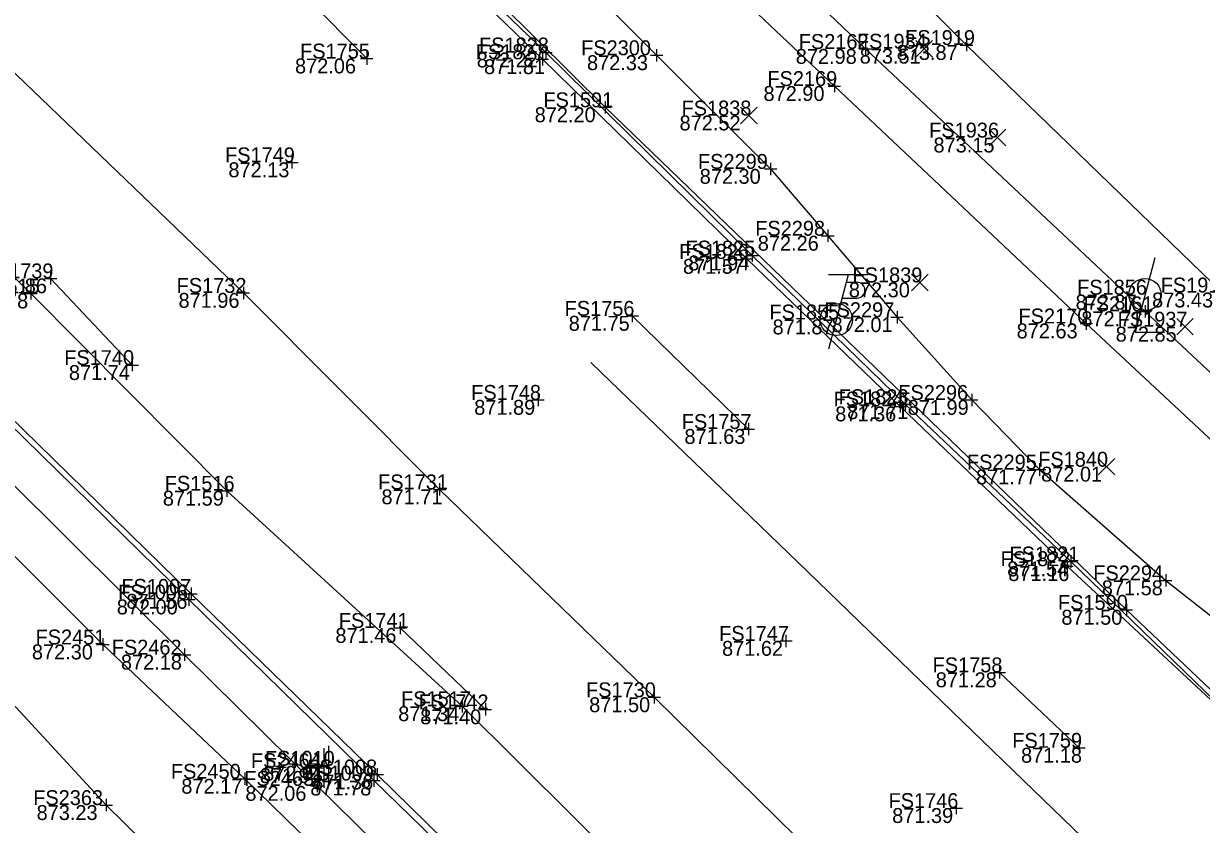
# Model space of a CAD drawing. Extents: x 1479420 to 1479833, y 379731 to 380103.
# Drawn here: x 1479498.2 to 1479593, y 379987.2 to 380051.7 of the extents above; entities that cross this region are included whole.
import ezdxf

# ---------------------------------------------------------------- set-up
doc = ezdxf.new("R2010")
doc.units = 0
for name, color, linetype in [('LT_X_Poles', 7, 'Continuous'), ('PM_X_Channelizing_Line', 7, 'Continuous'), ('PM_X_CL_Double_Solid', 7, 'Continuous'), ('PM_X_Lane_Line', 7, 'Continuous'), ('PV_X_Curb', 7, 'Continuous'), ('PV_X_Walk', 7, 'Continuous'), ('SN_X_Public', 7, 'Continuous'), ('SV_X_Break_Lines', 7, 'Continuous'), ('SV_X_Random_Point', 7, 'Continuous'), ('SV_X_Shot_Marker', 7, 'Continuous'), ('SV_X_Text_Elevation', 7, 'Continuous'), ('SV_X_Text_Name', 7, 'Continuous'), ('UT_X_Gas', 7, 'Continuous'), ('UT_X_Misc_Cells', 7, 'Continuous'), ('UT_X_Water', 7, 'Continuous')]:
    doc.layers.add(name, color=color, linetype=linetype)

msp = doc.modelspace()

# ---------------------------------------------------------------- linework, layer by layer
at = {"layer": 'LT_X_Poles'}
msp.add_lwpolyline([(1479589.196, 380032.83), (1479587.621, 380026.845), (1479589.984, 380026.845)], dxfattribs=at)
msp.add_circle((1479588.409, 380029.877), 1.3, dxfattribs=at)
at = {"layer": 'PM_X_Channelizing_Line'}
msp.add_lwpolyline([(1479582.673, 379963.806), (1479570.271, 379976.458), (1479548.912, 379997.457), (1479531.64, 380014.197), (1479515.852, 380030.017), (1479497.57, 380047.609), (1479484.703, 380060.356), (1479474.973, 380069.833)], dxfattribs=at)
at = {"layer": 'PM_X_CL_Double_Solid'}
msp.add_lwpolyline([(1479649.77, 379921.473), (1479632.094, 379938.759), (1479618.381, 379952.22), (1479598.438, 379971.627), (1479578.627, 379990.753), (1479560.467, 380008.345), (1479543.803, 380024.417)], dxfattribs=at)
at = {"layer": 'PM_X_Lane_Line'}
for p, q in [((1479518.914, 380055.834), (1479525.775, 380048.891)), ((1479500.335, 380031.188), (1479506.907, 380024.206)), ((1479547.143, 380028.17), (1479556.493, 380019.059)), ((1479528.47, 380003.039), (1479535.323, 379996.483)), ((1479576.693, 379999.465), (1479583.102, 379993.389))]:
    msp.add_line(p, q, dxfattribs=at)
at = {"layer": 'PV_X_Curb'}
for points in [[(1479795.994, 380033.189), (1479773.609, 380022.189), (1479753.08, 380012.28), (1479732.582, 380002.187), (1479709.578, 379990.944), (1479686.038, 379979.568), (1479675.424, 379995.638), (1479673.845, 379997.042), (1479672.388, 379997.402), (1479671.072, 379997.477), (1479668.749, 379997.507), (1479666.577, 379997.444), (1479665.261, 379997.435), (1479663.761, 379996.907), (1479662.621, 379996.118), (1479646.813, 379979.589), (1479631.39, 379994.413), (1479612.948, 380012.393), (1479594.615, 380030.048), (1479574.047, 380049.976), (1479559.355, 380064.639), (1479550.33, 380073.358), (1479530.481, 380092.839), (1479523.351, 380099.687)], [(1479620.557, 379971.482), (1479582.44, 380008.391), (1479569.122, 380021.057), (1479556.793, 380033.025), (1479540.187, 380049.375), (1479522.156, 380066.75), (1479503.679, 380084.635)], [(1479602.178, 379989.373), (1479582.142, 380008.015), (1479568.704, 380020.876), (1479556.358, 380032.756), (1479539.916, 380048.835), (1479521.67, 380066.459), (1479503.182, 380084.417)], [(1479465.217, 380050.646), (1479478.531, 380037.631), (1479495.524, 380020.938), (1479511.459, 380005.334), (1479526.353, 379990.752), (1479540.932, 379976.569), (1479555.934, 379961.972), (1479555.892, 379961.631), (1479559.685, 379957.777), (1479564.545, 379952.777), (1479567.017, 379949.687), (1479570.003, 379944.359), (1479571.368, 379941.515), (1479571.64, 379940.628), (1479572.403, 379938.2), (1479572.729, 379936.736), (1479572.917, 379935.416), (1479573.286, 379931.116), (1479573.281, 379927.358), (1479572.586, 379922.13), (1479571.403, 379917.504), (1479569.157, 379912.511), (1479566.948, 379909.055), (1479563.851, 379905.522)], [(1479465.43, 380051.173), (1479478.923, 380037.911), (1479495.631, 380021.426), (1479511.639, 380005.785), (1479526.613, 379991.238), (1479541.434, 379976.722), (1479556.225, 379962.402), (1479558.522, 379960.088), (1479562.263, 379956.631), (1479564.944, 379953.172), (1479567.55, 379949.792), (1479570.394, 379944.783), (1479571.863, 379941.541), (1479572.44, 379940.294), (1479572.888, 379938.328), (1479573.209, 379936.746), (1479573.486, 379935.414), (1479573.818, 379931.241), (1479573.756, 379927.245), (1479573.045, 379921.888), (1479571.771, 379917.234), (1479569.497, 379912.161), (1479567.166, 379908.643), (1479563.944, 379905.002)]]:
    msp.add_lwpolyline(points, dxfattribs=at)
at = {"layer": 'PV_X_Walk'}
for points in [[(1479608.139, 380010.055), (1479588.42, 380028.534), (1479565.918, 380049.66), (1479549.795, 380065.102), (1479530.811, 380082.977), (1479510.647, 380101.859)], [(1479508.898, 380098.739), (1479528.424, 380079.592), (1479545.906, 380063.234), (1479563.416, 380046.674), (1479583.683, 380027.557), (1479601.433, 380010.982), (1479618.885, 379994.721), (1479633.506, 379980.864), (1479639.156, 379975.367), (1479642.136, 379972.51), (1479646.219, 379969.763), (1479649.18, 379968.041), (1479652.865, 379966.819), (1479656.787, 379966.268), (1479660.633, 379966.347), (1479661.26, 379962.343), (1479661.797, 379958.407), (1479662.398, 379954.371), (1479663.052, 379950.601), (1479663.586, 379946.455), (1479663.663, 379946.474), (1479664.156, 379942.194)], [(1479459.693, 380050.631), (1479472.079, 380039.157), (1479482.634, 380028.96), (1479496.943, 380014.955), (1479511.111, 380000.888), (1479521.784, 379990.322), (1479535.54, 379976.798), (1479546.783, 379965.861), (1479553.984, 379958.805), (1479560.12, 379952.427), (1479566.081, 379946.058), (1479567.842, 379944.161), (1479569.592, 379942.392), (1479571.25, 379941.414)], [(1479571.225, 379941.406), (1479571.443, 379940.74), (1479572.055, 379938.942), (1479572.399, 379937.356), (1479572.583, 379936.247), (1479572.708, 379935.62), (1479569.085, 379935.113), (1479567.56, 379937.205), (1479566.035, 379939.554), (1479564.616, 379941.63), (1479559.488, 379947.364), (1479553.278, 379954.086), (1479540.659, 379966.748), (1479530.117, 379977.06), (1479515.964, 379990.896), (1479504.534, 380001.709), (1479490.824, 380015.396), (1479476.31, 380029.289), (1479463.443, 380042.077), (1479456.834, 380048.374)]]:
    msp.add_lwpolyline(points, dxfattribs=at)
at = {"layer": 'SN_X_Public'}
for p, q in [((1479522.707, 379993.541), (1479522.707, 379990.341)), ((1479522.311, 379993.353), (1479522.311, 379990.153)), ((1479522.311, 379991.753), (1479520.711, 379991.753)), ((1479522.707, 379991.941), (1479521.107, 379991.941))]:
    msp.add_line(p, q, dxfattribs=at)
at = {"layer": 'SV_X_Break_Lines'}
msp.add_lwpolyline([(1479534.387, 379905.648), (1479543.524, 379912.475), (1479551.336, 379918.185), (1479553.597, 379921.305), (1479553.861, 379925.501), (1479552.129, 379929.668), (1479547.926, 379935.993), (1479545.155, 379941.461), (1479539.822, 379948.42), (1479529.018, 379961.007), (1479520.635, 379970.728), (1479513.841, 379979.888), (1479504.809, 379988.776), (1479495.63, 379998.694), (1479487.89, 380006.933), (1479478.402, 380016.952), (1479472.872, 380022.536)], dxfattribs=at)
at = {"layer": 'SV_X_Random_Point'}
for p, q in [((1479569.971, 380049.013), (1479571.305, 380050.348)), ((1479569.971, 380050.348), (1479571.305, 380049.013)), ((1479555.859, 380043.634), (1479557.193, 380044.969)), ((1479555.859, 380044.969), (1479557.193, 380043.634)), ((1479575.87, 380041.857), (1479577.204, 380043.192)), ((1479575.87, 380043.192), (1479577.204, 380041.857)), ((1479569.618, 380030.197), (1479570.952, 380031.532)), ((1479569.618, 380031.532), (1479570.952, 380030.197)), ((1479590.967, 380026.63), (1479592.301, 380027.965)), ((1479590.967, 380027.965), (1479592.301, 380026.63)), ((1479584.65, 380015.357), (1479585.984, 380016.692)), ((1479584.65, 380016.692), (1479585.984, 380015.357))]:
    msp.add_line(p, q, dxfattribs=at)
at = {"layer": 'SV_X_Shot_Marker'}
for p, q in [((1479574.047, 380050.476), (1479574.047, 380049.476)), ((1479540.187, 380049.875), (1479540.187, 380048.875)), ((1479549.105, 380049.654), (1479549.105, 380048.654)), ((1479565.418, 380049.66), (1479566.418, 380049.66)), ((1479565.918, 380050.16), (1479565.918, 380049.16)), ((1479565.918, 380049.66), (1479565.918, 380049.66)), ((1479573.547, 380049.976), (1479574.547, 380049.976)), ((1479574.047, 380049.976), (1479574.047, 380049.976)), ((1479525.275, 380048.891), (1479526.275, 380048.891)), ((1479525.775, 380049.391), (1479525.775, 380048.391)), ((1479525.775, 380048.891), (1479525.775, 380048.891)), ((1479539.416, 380048.835), (1479540.416, 380048.835)), ((1479539.687, 380049.375), (1479540.687, 380049.375)), ((1479539.916, 380049.335), (1479539.916, 380048.335)), ((1479539.916, 380048.835), (1479539.916, 380048.835)), ((1479540.187, 380049.375), (1479540.187, 380049.375)), ((1479548.605, 380049.154), (1479549.605, 380049.154)), ((1479549.105, 380049.154), (1479549.105, 380049.154)), ((1479562.916, 380046.674), (1479563.916, 380046.674)), ((1479563.416, 380047.174), (1479563.416, 380046.174)), ((1479563.416, 380046.674), (1479563.416, 380046.674)), ((1479544.461, 380044.963), (1479545.461, 380044.963)), ((1479544.961, 380045.463), (1479544.961, 380044.463)), ((1479544.961, 380044.963), (1479544.961, 380044.963)), ((1479519.756, 380041.031), (1479519.756, 380040.031)), ((1479519.256, 380040.531), (1479520.256, 380040.531)), ((1479519.756, 380040.531), (1479519.756, 380040.531)), ((1479557.782, 380040.003), (1479558.782, 380040.003)), ((1479558.282, 380040.503), (1479558.282, 380039.503)), ((1479558.282, 380040.003), (1479558.282, 380040.003)), ((1479562.389, 380034.62), (1479563.389, 380034.62)), ((1479562.889, 380035.12), (1479562.889, 380034.12)), ((1479562.889, 380034.62), (1479562.889, 380034.62)), ((1479556.793, 380033.525), (1479556.793, 380032.525)), ((1479555.858, 380032.756), (1479556.858, 380032.756)), ((1479556.293, 380033.025), (1479557.293, 380033.025)), ((1479556.358, 380033.256), (1479556.358, 380032.256)), ((1479556.358, 380032.756), (1479556.358, 380032.756)), ((1479556.793, 380033.025), (1479556.793, 380033.025)), ((1479500.335, 380031.688), (1479500.335, 380030.688)), ((1479498.741, 380030.474), (1479498.741, 380029.474)), ((1479499.835, 380031.188), (1479500.835, 380031.188)), ((1479500.335, 380031.188), (1479500.335, 380031.188)), ((1479515.852, 380030.517), (1479515.852, 380029.517)), ((1479498.241, 380029.974), (1479499.241, 380029.974)), ((1479498.741, 380029.974), (1479498.741, 380029.974)), ((1479515.352, 380030.017), (1479516.352, 380030.017)), ((1479515.852, 380030.017), (1479515.852, 380030.017)), ((1479547.143, 380028.67), (1479547.143, 380027.67)), ((1479588.42, 380029.034), (1479588.42, 380028.034)), ((1479546.643, 380028.17), (1479547.643, 380028.17)), ((1479547.143, 380028.17), (1479547.143, 380028.17)), ((1479567.953, 380028.062), (1479568.953, 380028.062)), ((1479568.453, 380028.562), (1479568.453, 380027.562)), ((1479568.453, 380028.062), (1479568.453, 380028.062)), ((1479583.683, 380028.057), (1479583.683, 380027.057)), ((1479587.92, 380028.534), (1479588.92, 380028.534)), ((1479588.42, 380028.534), (1479588.42, 380028.534)), ((1479583.183, 380027.557), (1479584.183, 380027.557)), ((1479583.683, 380027.557), (1479583.683, 380027.557)), ((1479506.407, 380024.206), (1479507.407, 380024.206)), ((1479506.907, 380024.706), (1479506.907, 380023.706)), ((1479506.907, 380024.206), (1479506.907, 380024.206)), ((1479539.067, 380021.404), (1479540.067, 380021.404)), ((1479539.567, 380021.904), (1479539.567, 380020.904)), ((1479539.567, 380021.404), (1479539.567, 380021.404)), ((1479568.622, 380021.057), (1479569.622, 380021.057)), ((1479568.704, 380021.376), (1479568.704, 380020.376)), ((1479569.122, 380021.557), (1479569.122, 380020.557)), ((1479569.122, 380021.057), (1479569.122, 380021.057)), ((1479573.971, 380021.4), (1479574.971, 380021.4)), ((1479574.471, 380021.9), (1479574.471, 380020.9)), ((1479574.471, 380021.4), (1479574.471, 380021.4)), ((1479568.204, 380020.876), (1479569.204, 380020.876)), ((1479568.704, 380020.876), (1479568.704, 380020.876)), ((1479556.493, 380019.559), (1479556.493, 380018.559)), ((1479555.993, 380019.059), (1479556.993, 380019.059)), ((1479556.493, 380019.059), (1479556.493, 380019.059)), ((1479579.923, 380016.298), (1479579.923, 380015.298)), ((1479579.423, 380015.798), (1479580.423, 380015.798)), ((1479579.923, 380015.798), (1479579.923, 380015.798)), ((1479514.505, 380014.586), (1479514.505, 380013.586)), ((1479531.64, 380014.697), (1479531.64, 380013.697)), ((1479514.005, 380014.086), (1479515.005, 380014.086)), ((1479514.505, 380014.086), (1479514.505, 380014.086)), ((1479531.14, 380014.197), (1479532.14, 380014.197)), ((1479531.64, 380014.197), (1479531.64, 380014.197)), ((1479582.44, 380008.891), (1479582.44, 380007.891)), ((1479581.642, 380008.015), (1479582.642, 380008.015)), ((1479581.94, 380008.391), (1479582.94, 380008.391)), ((1479582.142, 380008.515), (1479582.142, 380007.515)), ((1479582.142, 380008.015), (1479582.142, 380008.015)), ((1479582.44, 380008.391), (1479582.44, 380008.391)), ((1479589.576, 380006.869), (1479590.576, 380006.869)), ((1479590.076, 380007.369), (1479590.076, 380006.369)), ((1479590.076, 380006.869), (1479590.076, 380006.869)), ((1479511.459, 380005.834), (1479511.459, 380004.834)), ((1479511.639, 380006.285), (1479511.639, 380005.285)), ((1479510.959, 380005.334), (1479511.959, 380005.334)), ((1479511.139, 380005.785), (1479512.139, 380005.785)), ((1479511.459, 380005.334), (1479511.459, 380005.334)), ((1479511.639, 380005.785), (1479511.639, 380005.785)), ((1479586.915, 380005.001), (1479586.915, 380004.001)), ((1479586.415, 380004.501), (1479587.415, 380004.501)), ((1479586.915, 380004.501), (1479586.915, 380004.501)), ((1479527.97, 380003.039), (1479528.97, 380003.039)), ((1479528.47, 380003.539), (1479528.47, 380002.539)), ((1479528.47, 380003.039), (1479528.47, 380003.039)), ((1479504.534, 380002.209), (1479504.534, 380001.209)), ((1479559.51, 380002.497), (1479559.51, 380001.497)), ((1479504.034, 380001.709), (1479505.034, 380001.709)), ((1479504.534, 380001.709), (1479504.534, 380001.709)), ((1479511.111, 380001.388), (1479511.111, 380000.388)), ((1479559.01, 380001.997), (1479560.01, 380001.997)), ((1479559.51, 380001.997), (1479559.51, 380001.997)), ((1479510.611, 380000.888), (1479511.611, 380000.888)), ((1479511.111, 380000.888), (1479511.111, 380000.888)), ((1479576.193, 379999.465), (1479577.193, 379999.465)), ((1479576.693, 379999.965), (1479576.693, 379998.965)), ((1479576.693, 379999.465), (1479576.693, 379999.465)), ((1479548.412, 379997.457), (1479549.412, 379997.457)), ((1479548.912, 379997.957), (1479548.912, 379996.957)), ((1479548.912, 379997.457), (1479548.912, 379997.457)), ((1479532.948, 379996.735), (1479533.948, 379996.735)), ((1479533.448, 379997.235), (1479533.448, 379996.235)), ((1479533.448, 379996.735), (1479533.448, 379996.735)), ((1479534.823, 379996.483), (1479535.823, 379996.483)), ((1479535.323, 379996.983), (1479535.323, 379995.983)), ((1479535.323, 379996.483), (1479535.323, 379996.483)), ((1479583.102, 379993.889), (1479583.102, 379992.889)), ((1479582.602, 379993.389), (1479583.602, 379993.389)), ((1479583.102, 379993.389), (1479583.102, 379993.389)), ((1479526.613, 379991.738), (1479526.613, 379990.738)), ((1479515.464, 379990.896), (1479516.464, 379990.896)), ((1479515.964, 379991.396), (1479515.964, 379990.396)), ((1479515.964, 379990.896), (1479515.964, 379990.896)), ((1479521.784, 379990.822), (1479521.784, 379989.822)), ((1479525.853, 379990.752), (1479526.853, 379990.752)), ((1479526.113, 379991.238), (1479527.113, 379991.238)), ((1479526.353, 379991.252), (1479526.353, 379990.252)), ((1479526.353, 379990.752), (1479526.353, 379990.752)), ((1479526.613, 379991.238), (1479526.613, 379991.238)), ((1479521.284, 379990.322), (1479522.284, 379990.322)), ((1479521.784, 379990.322), (1479521.784, 379990.322)), ((1479504.309, 379988.776), (1479505.309, 379988.776)), ((1479504.809, 379989.276), (1479504.809, 379988.276)), ((1479504.809, 379988.776), (1479504.809, 379988.776)), ((1479573.223, 379989.036), (1479573.223, 379988.036)), ((1479572.723, 379988.536), (1479573.723, 379988.536)), ((1479573.223, 379988.536), (1479573.223, 379988.536))]:
    msp.add_line(p, q, dxfattribs=at)
at = {"layer": 'UT_X_Gas'}
msp.add_lwpolyline([(1479505.105, 380092.371), (1479512.951, 380084.517), (1479521.671, 380075.794), (1479529.969, 380067.611), (1479539.245, 380059.043), (1479549.105, 380049.154), (1479558.282, 380040.003), (1479562.889, 380034.62), (1479568.453, 380028.062), (1479574.471, 380021.4), (1479579.923, 380015.798), (1479590.076, 380006.869), (1479598.835, 379999.983)], dxfattribs=at)
at = {"layer": 'UT_X_Misc_Cells'}
for p, q in [((1479564.532, 380031.477), (1479562.926, 380025.477)), ((1479566.132, 380031.477), (1479562.932, 380031.477)), ((1479564.372, 380030.877), (1479565.222, 380030.877)), ((1479564.031, 380029.602), (1479565.222, 380029.602))]:
    msp.add_line(p, q, dxfattribs=at)
msp.add_circle((1479563.569, 380027.877), 1.3, dxfattribs=at)
msp.add_arc((1479565.235, 380030.24), 0.638, 268.8767, 91.1233, dxfattribs=at)
at = {"layer": 'UT_X_Water'}
for points in [[(1479502.338, 380087.071), (1479522.598, 380067.181), (1479544.961, 380044.963), (1479586.915, 380004.501), (1479604.754, 379987.567)], [(1479473.217, 380054.881), (1479498.741, 380029.974), (1479514.505, 380014.086), (1479533.448, 379996.735), (1479556.003, 379974.319), (1479574.861, 379956.271), (1479584.403, 379947.432), (1479599.597, 379932.819), (1479630.106, 379903.783), (1479644.769, 379889.722), (1479654.209, 379882.356), (1479664.266, 379872.629), (1479692.509, 379845.847), (1479712.672, 379826.686), (1479730.739, 379809.85), (1479753.15, 379788.309), (1479771.842, 379770.542), (1479781.678, 379761.101)]]:
    msp.add_lwpolyline(points, dxfattribs=at)

# ---------------------------------------------------------------- texts
at = {"layer": 'SV_X_Text_Elevation'}
for s, p in [('872.98', (1479560.306, 380048.46)), ('873.51', (1479565.45, 380048.481)), ('873.87', (1479568.425, 380048.776)), ('872.06', (1479520.002, 380047.691)), ('872.22', (1479534.631, 380048.175)), ('871.81', (1479535.22, 380047.635)), ('872.33', (1479543.502, 380047.954)), ('872.90', (1479557.709, 380045.474)), ('872.20', (1479539.292, 380043.763)), ('872.52', (1479550.952, 380043.102)), ('873.15', (1479571.388, 380041.325)), ('872.13', (1479514.645, 380039.331)), ('872.30', (1479552.575, 380038.803)), ('872.26', (1479557.248, 380033.42)), ('871.57', (1479551.228, 380031.556)), ('871.94', (1479551.654, 380031.825)), ('871.86', (1479495.13, 380029.988)), ('872.30', (1479564.578, 380029.664)), ('871.78', (1479493.621, 380028.774)), ('871.96', (1479510.628, 380028.817)), ('872.87', (1479582.825, 380028.677)), ('873.43', (1479588.984, 380028.848)), ('871.75', (1479542.032, 380026.97)), ('871.87', (1479558.439, 380026.677)), ('872.01', (1479563.19, 380026.862)), ('872.71', (1479583.289, 380027.334)), ('872.63', (1479578.08, 380026.357)), ('872.85', (1479586.05, 380026.097)), ('871.74', (1479501.806, 380023.006)), ('871.89', (1479534.428, 380020.204)), ('871.71', (1479564.445, 380019.857)), ('871.99', (1479569.313, 380020.2)), ('871.36', (1479563.48, 380019.676)), ('871.63', (1479551.344, 380017.859)), ('871.77', (1479574.812, 380014.598)), ('872.01', (1479580.054, 380014.824)), ('871.59', (1479509.366, 380012.886)), ('871.71', (1479526.963, 380012.997)), ('871.54', (1479577.32, 380007.191)), ('871.16', (1479577.41, 380006.815)), ('871.58', (1479584.937, 380005.669)), ('872.00', (1479505.658, 380004.134)), ('871.56', (1479506.434, 380004.585)), ('871.50', (1479581.681, 380003.301)), ('871.46', (1479523.255, 380001.839)), ('872.30', (1479498.827, 380000.509)), ('871.62', (1479554.371, 380000.797)), ('872.18', (1479505.991, 379999.688)), ('871.28', (1479571.573, 379998.265)), ('871.50', (1479543.678, 379996.257)), ('871.34', (1479528.309, 379995.535)), ('871.40', (1479530.08, 379995.283)), ('871.18', (1479578.436, 379992.189)), ('871.94', (1479517.172, 379990.553)), ('872.01', (1479517.444, 379990.741)), ('872.17', (1479510.853, 379989.696)), ('871.78', (1479521.233, 379989.552)), ('871.36', (1479521.389, 379990.038)), ('872.06', (1479516.011, 379989.122)), ('873.23', (1479499.206, 379987.576)), ('871.39', (1479568.065, 379987.336))]:
    msp.add_text(s, height=1.2, dxfattribs=at).set_placement(p)
at = {"layer": 'SV_X_Text_Name'}
for s, p in [('FS1828', (1479534.812, 380049.375)), ('FS2300', (1479543.03, 380049.154)), ('FS2162', (1479560.543, 380049.66)), ('FS1934', (1479565.225, 380049.681)), ('FS1919', (1479569.107, 380049.976)), ('FS1755', (1479520.409, 380048.891)), ('FS1827', (1479534.55, 380048.835)), ('FS2169', (1479558.022, 380046.674)), ('FS1591', (1479539.991, 380044.963)), ('FS1838', (1479551.113, 380044.302)), ('FS1936', (1479571.039, 380042.525)), ('FS1749', (1479514.371, 380040.531)), ('FS2299', (1479552.434, 380040.003)), ('FS2298', (1479557.041, 380034.62)), ('FS1826', (1479550.917, 380032.756)), ('FS1825', (1479551.427, 380033.025)), ('FS1739', (1479494.941, 380031.188)), ('FS1839', (1479564.872, 380030.864)), ('FS1515', (1479493.829, 380029.974)), ('FS1732', (1479510.477, 380030.017)), ('FS1856', (1479582.949, 380029.877)), ('FS1918', (1479589.675, 380030.048)), ('FS2161', (1479583.469, 380028.534)), ('FS1756', (1479541.702, 380028.17)), ('FS1855', (1479558.184, 380027.877)), ('FS2297', (1479562.614, 380028.062)), ('FS2170', (1479578.232, 380027.557)), ('FS1937', (1479586.211, 380027.297)), ('FS1740', (1479501.428, 380024.206)), ('FS1748', (1479534.182, 380021.404)), ('FS1824', (1479563.348, 380020.876)), ('FS1823', (1479563.756, 380021.057)), ('FS2296', (1479568.557, 380021.4)), ('FS1757', (1479551.127, 380019.059)), ('FS1840', (1479579.819, 380016.024)), ('FS2295', (1479574.084, 380015.798)), ('FS1516', (1479509.518, 380014.086)), ('FS1731', (1479526.689, 380014.197)), ('FS1821', (1479577.508, 380008.391)), ('FS1822', (1479576.786, 380008.015)), ('FS2294', (1479584.247, 380006.869)), ('FS1007', (1479506.027, 380005.785)), ('FS1006', (1479505.772, 380005.334)), ('FS1590', (1479581.407, 380004.501)), ('FS1741', (1479523.529, 380003.039)), ('FS1747', (1479554.135, 380001.997)), ('FS2451', (1479499.12, 380001.709)), ('FS2462', (1479505.253, 380000.888)), ('FS1758', (1479571.318, 379999.465)), ('FS1730', (1479543.423, 379997.457)), ('FS1517', (1479528.536, 379996.735)), ('FS1742', (1479529.957, 379996.483)), ('FS1759', (1479577.727, 379993.389)), ('FS2464', (1479516.453, 379991.753)), ('FS1010', (1479517.578, 379991.941)), ('FS2450', (1479510.012, 379990.896)), ('FS1009', (1479520.732, 379990.752)), ('FS1008', (1479520.992, 379991.238)), ('FS2463', (1479515.917, 379990.322)), ('FS2363', (1479498.932, 379988.776)), ('FS1746', (1479567.772, 379988.536))]:
    msp.add_text(s, height=1.2, dxfattribs=at).set_placement(p)

doc.saveas('drawing.dxf')
